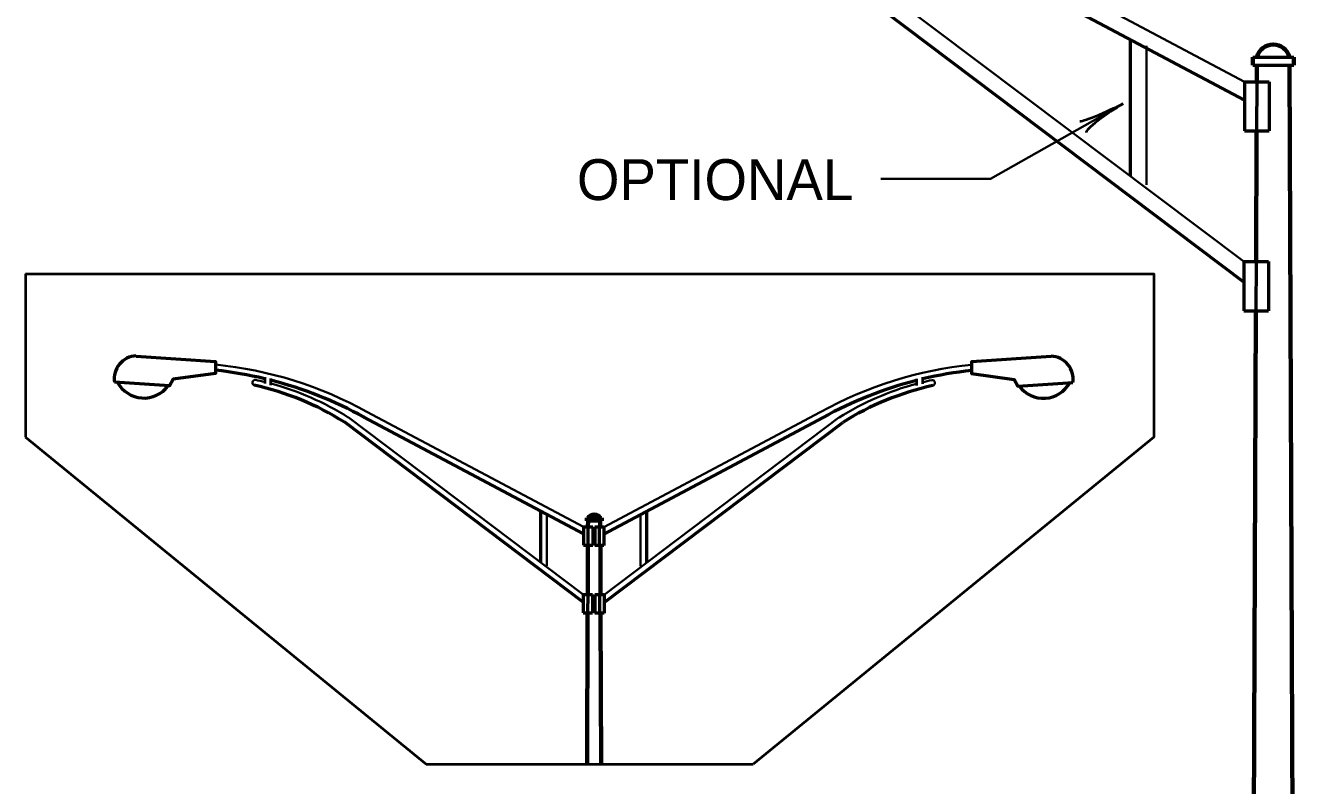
# Model space of a CAD drawing. Extents: x -20 to 693, y -19 to 435.
# Drawn here: x 60 to 139.1, y 342.3 to 389.5 of the extents above; entities that cross this region are included whole.
import ezdxf

# ---------------------------------------------------------------- set-up
doc = ezdxf.new("R2010")
doc.units = 0
doc.layers.add('1', color=7, linetype='Continuous', lineweight=53)

msp = doc.modelspace()

# ---------------------------------------------------------------- linework, layer by layer
at = {"layer": '1', "lineweight": 35}
for p, q in [((135.783, 386.027), (99.903, 405.127)), ((135.743, 374.867), (96.803, 404.207)), ((129.703, 388.267), (129.703, 379.627)), ((94.703, 358.367), (81.243, 365.527)), ((95.963, 358.347), (109.423, 365.507)), ((94.683, 354.167), (80.083, 365.187)), ((95.983, 354.147), (110.583, 365.167)), ((92.423, 359.187), (92.423, 355.947)), ((98.243, 359.167), (98.243, 355.927))]:
    msp.add_line(p, q, dxfattribs=at)
at = {"layer": '1'}
for p, q in [((135.783, 384.887), (99.443, 404.207)), ((135.743, 373.587), (96.183, 403.407)), ((128.683, 388.667), (128.683, 380.187)), ((136.303, 387.567), (138.843, 387.567)), ((136.303, 387.067), (138.843, 387.067)), ((135.783, 386.027), (137.323, 386.027)), ((135.783, 386.027), (135.783, 382.987)), ((136.543, 386.027), (136.523, 382.987)), ((137.323, 386.027), (137.323, 382.987)), ((135.783, 382.987), (137.323, 382.987)), ((135.743, 374.867), (137.283, 374.867)), ((135.743, 374.867), (135.743, 371.807)), ((136.503, 374.867), (136.483, 371.807)), ((137.283, 374.867), (137.283, 371.807)), ((135.743, 371.807), (137.283, 371.807)), ((94.683, 353.687), (79.863, 364.887)), ((94.703, 357.927), (81.063, 365.187)), ((95.963, 357.907), (109.603, 365.167)), ((95.983, 353.667), (110.823, 364.867)), ((92.043, 359.367), (92.043, 356.167)), ((98.623, 359.347), (98.623, 356.147)), ((94.703, 358.367), (95.283, 358.367)), ((94.703, 358.367), (94.703, 357.227)), ((94.903, 358.927), (95.843, 358.927)), ((94.903, 358.747), (95.843, 358.747)), ((94.983, 358.367), (94.983, 357.227)), ((95.283, 358.367), (95.283, 357.227)), ((95.963, 358.347), (95.403, 358.347)), ((95.403, 358.347), (95.403, 357.207)), ((95.683, 358.347), (95.683, 357.207)), ((95.963, 358.347), (95.963, 357.207)), ((94.703, 357.227), (95.283, 357.227)), ((95.963, 357.207), (95.403, 357.207)), ((94.683, 354.167), (95.263, 354.167)), ((94.683, 354.167), (94.683, 353.027)), ((94.983, 354.167), (94.963, 353.027)), ((95.263, 354.167), (95.263, 353.027)), ((95.983, 354.147), (95.403, 354.147)), ((95.403, 354.147), (95.403, 353.007)), ((95.703, 354.147), (95.703, 353.007)), ((95.983, 354.147), (95.983, 353.007)), ((94.683, 353.027), (95.263, 353.027)), ((95.983, 353.007), (95.403, 353.007))]:
    msp.add_line(p, q, dxfattribs=at)
at = {"layer": '1', "lineweight": 70}
for p, q in [((136.303, 387.567), (136.303, 387.067)), ((138.843, 387.567), (138.843, 387.067)), ((136.543, 387.067), (136.543, 386.027)), ((138.583, 387.067), (139.083, 261.067)), ((136.523, 382.987), (136.503, 374.867)), ((136.483, 371.807), (136.043, 261.067)), ((94.903, 358.927), (94.903, 358.747)), ((95.003, 358.747), (94.983, 358.367)), ((95.743, 358.747), (95.743, 358.347)), ((95.843, 358.927), (95.843, 358.747)), ((94.983, 357.227), (94.983, 354.167)), ((95.763, 357.207), (95.763, 354.147)), ((94.963, 353.027), (94.943, 343.627)), ((95.763, 353.007), (95.803, 343.627))]:
    msp.add_line(p, q, dxfattribs=at)
at = {"layer": '1', "lineweight": 40}
for p, q in [((60.023, 374.107), (60.023, 363.947)), ((74.903, 367.667), (74.903, 367.287)), ((115.783, 367.667), (115.783, 367.267)), ((75.263, 367.587), (75.263, 367.187)), ((115.403, 367.567), (115.403, 367.167)), ((60.023, 363.947), (84.923, 343.627)), ((130.143, 363.947), (105.243, 343.627)), ((84.923, 343.627), (105.243, 343.627))]:
    msp.add_line(p, q, dxfattribs=at)
at = {"layer": '1', "lineweight": 35}
for points in [[(128.237, 384.67), (119.998, 380.012), (113.193, 380.012)], [(66.903, 368.987), (71.843, 368.647), (71.843, 367.907), (69.203, 367.547), (68.983, 367.127), (65.563, 367.367), (65.559, 367.362)], [(118.823, 367.907), (118.823, 368.627), (123.763, 368.967)], [(125.123, 367.347), (121.703, 367.107), (121.463, 367.527), (118.823, 367.907)]]:
    msp.add_lwpolyline(points, dxfattribs=at)
at = {"layer": '1', "lineweight": 40}
msp.add_lwpolyline([(60.023, 374.107), (130.143, 374.107), (130.143, 363.947)], dxfattribs=at)
at = {"layer": '1'}
for points in [[(66.903, 368.987), (71.843, 368.647), (71.843, 367.907), (69.203, 367.547), (68.983, 367.127), (65.563, 367.367)], [(123.763, 368.967), (118.823, 368.627), (118.823, 367.907), (121.463, 367.527), (121.703, 367.107), (125.123, 367.347)]]:
    msp.add_lwpolyline(points, dxfattribs=at)
at = {"layer": '1', "lineweight": 70}
for centre, radius, start, end in [((137.572, 387.312), 1.044, 13.87704, 166.12296), ((95.373, 358.669), 0.464, 34.90646, 145.09354)]:
    msp.add_arc(centre, radius, start, end, dxfattribs=at)
at = {"layer": '1'}
for centre, radius, start, end in [((66.949, 367.589), 1.408, 91.83971, 189.27341), ((123.723, 367.571), 1.408, 350.72659, 88.16029), ((69.203, 343.753), 24.495, 76.56687, 83.80757), ((121.469, 343.736), 24.495, 96.19243, 103.43312), ((67.387, 368.242), 1.866, 208.61261, 323.3862), ((70.529, 350.104), 17.466, 57.73839, 77.70604), ((69.203, 343.753), 24.495, 61.02434, 75.64876), ((121.469, 343.736), 24.495, 104.35124, 118.97566), ((120.143, 350.087), 17.466, 102.29396, 122.26161), ((123.285, 368.225), 1.866, 216.6138, 331.38739)]:
    msp.add_arc(centre, radius, start, end, dxfattribs=at)
at = {"layer": '1', "lineweight": 35}
for centre, radius, start, end in [((66.949, 367.589), 1.408, 91.83971, 189.27341), ((69.382, 344.089), 24.495, 61.02434, 84.2283), ((121.29, 344.072), 24.495, 95.7717, 118.97566), ((123.723, 367.571), 1.408, 350.72659, 88.16029), ((74.299, 367.335), 0.173, 82.46148, 252.95617), ((70.758, 350.408), 17.466, 76.30626, 78.22847), ((70.758, 350.408), 17.466, 57.73839, 75.01614), ((119.914, 350.391), 17.466, 104.98386, 122.26161), ((119.914, 350.391), 17.466, 101.77153, 103.69374), ((116.373, 367.318), 0.173, 287.04383, 97.53852)]:
    msp.add_arc(centre, radius, start, end, dxfattribs=at)
at = {"layer": '1', "lineweight": 40}
for centre, major_axis, ratio, start_param, end_param in [((127.157, 384.303), (-1.615, -0.712), 0.07063, 6.282307, 8.559703), ((127.423, 383.892), (1.478, 1.015), 0.122415, 0.896353, 3.141593)]:
    msp.add_ellipse(centre, major_axis=major_axis, ratio=ratio, start_param=start_param, end_param=end_param, dxfattribs=at)

# ---------------------------------------------------------------- texts
at = {"layer": '1'}
msp.add_text('OPTIONAL', height=2.54, dxfattribs=at).set_placement((94.299, 378.683))

doc.saveas('drawing.dxf')
